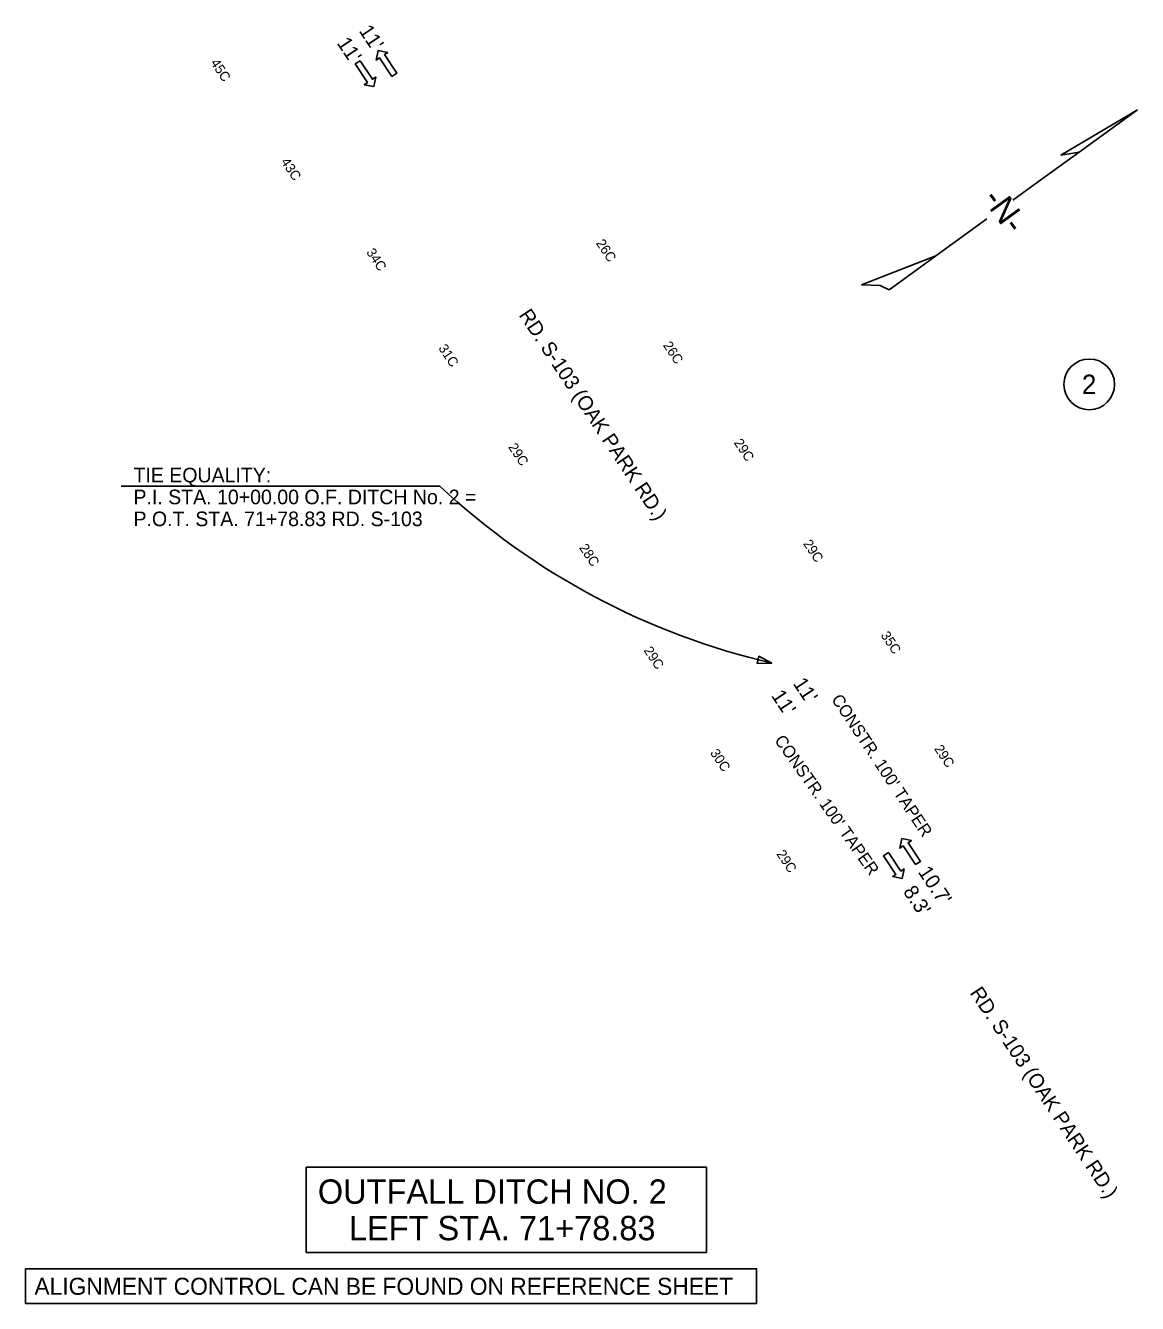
# Model space of a CAD drawing. Extents: x 1964850 to 1967424, y 1116563 to 1122204.
# Drawn here: x 1966637 to 1967094, y 1121679 to 1122204 of the extents above; entities that cross this region are included whole.
import ezdxf

# ---------------------------------------------------------------- set-up
doc = ezdxf.new("R2010")
doc.units = 0
for name, color, linetype in [('RD_EX_DV_TX_Prop', 7, 'Continuous'), ('RD_EX_Misc', 7, 'Continuous'), ('RD_HC_Data', 7, 'Continuous'), ('RD_PD_Final_LnLine', 7, 'Continuous'), ('RD_PD_Final_TX', 7, 'Continuous'), ('RD_PD_TX_CstnLmt', 7, 'Continuous'), ('RD_Sketch1', 7, 'Continuous'), ('RD_TX_Misc2', 7, 'Continuous'), ('RD_TX_RoadID', 7, 'Continuous')]:
    doc.layers.add(name, color=color, linetype=linetype)

msp = doc.modelspace()

# ---------------------------------------------------------------- linework, layer by layer
at = {"layer": 'RD_EX_DV_TX_Prop'}
msp.add_circle((1967074, 1122056.86), 10.43, dxfattribs=at)
at = {"layer": 'RD_EX_Misc'}
for p, q in [((1967062.37, 1122151.06), (1967093.8, 1122169.71)), ((1967093.8, 1122169.71), (1967069.8, 1122152.32)), ((1967069.8, 1122152.32), (1967053.16, 1122140.27)), ((1967069.8, 1122152.32), (1967062.37, 1122151.06)), ((1967053.16, 1122140.27), (1967042.55, 1122132.58)), ((1967031.96, 1122124.91), (1967010.99, 1122109.72)), ((1966980.45, 1122097.77), (1967010.99, 1122109.72)), ((1967007.81, 1122107.41), (1966991.74, 1122095.77)), ((1967010.99, 1122109.72), (1967007.81, 1122107.41))]:
    msp.add_line(p, q, dxfattribs=at)
msp.add_lwpolyline([(1966991.74, 1122095.77), (1966988.09, 1122097.5), (1966980.45, 1122097.77)], dxfattribs=at)
at = {"layer": 'RD_HC_Data'}
msp.add_line((1966807.1, 1122015.09), (1966676.23, 1122015.09), dxfattribs=at)
msp.add_lwpolyline([(1966937.53, 1121942.12), (1966943.53, 1121942.33), (1966938.23, 1121945.15)], close=True, dxfattribs=at)
msp.add_arc((1967010.89, 1122232.89), 298.27, 226.9031, 256.9482, dxfattribs=at)
at = {"layer": 'RD_PD_Final_LnLine'}
for points in [[(1966774.32, 1122189.89), (1966772.32, 1122188.56), (1966777.4, 1122180.93), (1966776.05, 1122180.02), (1966779.97, 1122179.24), (1966780.76, 1122183.16), (1966779.4, 1122182.26)], [(1966787.44, 1122183.43), (1966789.44, 1122184.76), (1966784.36, 1122192.39), (1966785.71, 1122193.3), (1966781.79, 1122194.08), (1966781, 1122190.16), (1966782.36, 1122191.06)], [(1967002.64, 1121859.5), (1967004.64, 1121860.83), (1966999.56, 1121868.47), (1967000.92, 1121869.37), (1966996.99, 1121870.16), (1966996.21, 1121866.24), (1966997.56, 1121867.14)], [(1966991.49, 1121864.44), (1966989.49, 1121863.11), (1966994.58, 1121855.47), (1966993.22, 1121854.57), (1966997.14, 1121853.78), (1966997.93, 1121857.71), (1966996.57, 1121856.8)]]:
    msp.add_lwpolyline(points, close=True, dxfattribs=at)
at = {"layer": 'RD_Sketch1'}
msp.add_lwpolyline([(1966636.88, 1121693.39), (1966937.31, 1121693.39), (1966937.31, 1121679.13), (1966636.88, 1121679.13)], close=True, dxfattribs=at)
at = {"layer": 'RD_TX_Misc2'}
msp.add_lwpolyline([(1966752.2, 1121735.1), (1966916.66, 1121735.1), (1966916.66, 1121700.1), (1966752.2, 1121700.1)], close=True, dxfattribs=at)

# ---------------------------------------------------------------- texts
at = {"layer": 'RD_EX_DV_TX_Prop'}
msp.add_text('2', height=8, dxfattribs=at).set_placement((1967070.98, 1122052.86))
at = {"layer": 'RD_EX_Misc'}
msp.add_text('-N-', height=10, rotation=305.9228, dxfattribs=at).set_placement((1967029.94, 1122133.06))
at = {"layer": 'RD_HC_Data'}
for s, p in [('TIE EQUALITY:', (1966681.23, 1122016.59)), ('P.I. STA. 10+00.00 O.F. DITCH No. 2 =', (1966681.23, 1122007.59)), ('P.O.T. STA. 71+78.83 RD. S-103', (1966681.23, 1121998.59))]:
    msp.add_text(s, height=6, dxfattribs=at).set_placement(p)
at = {"layer": 'RD_PD_Final_TX'}
for s, height, rotation, p in [("11'", 6, 303.6494, (1966773.67, 1122202.19)), ("11'", 6, 303.6494, (1966764.6, 1122197.13)), ("11'", 6, 303.6494, (1966952.05, 1121933.92)), ("11'", 6, 303.6494, (1966943.12, 1121928.91)), ("CONSTR. 100' TAPER", 5, 303.5003, (1966967.84, 1121927.46)), ("CONSTR. 100' TAPER", 5, 305.2108, (1966944.4, 1121910.58)), ("10.7'", 6, 303.6494, (1967003.41, 1121856.47)), ("8.3'", 6, 303.6494, (1966997.29, 1121848.39))]:
    msp.add_text(s, height=height, rotation=rotation, dxfattribs=at).set_placement(p)
at = {"layer": 'RD_PD_TX_CstnLmt'}
for s, p in [('45C', (1966712.69, 1122189.02)), ('43C', (1966741.63, 1122148.37)), ('26C', (1966871.12, 1122114.89)), ('34C', (1966776.73, 1122111.17)), ('31C', (1966806.36, 1122071.76)), ('26C', (1966898.67, 1122072.92)), ('29C', (1966835.07, 1122031.09)), ('29C', (1966927.8, 1122032.91)), ('28C', (1966864.2, 1121989.74)), ('29C', (1966956.25, 1121991.43)), ('35C', (1966988.15, 1121953.75)), ('29C', (1966890.74, 1121947.5)), ('30C', (1966918.03, 1121905.42)), ('29C', (1967010.11, 1121907.11)), ('29C', (1966945.29, 1121863.87))]:
    msp.add_text(s, height=4, rotation=303.6494, dxfattribs=at).set_placement(p)
at = {"layer": 'RD_Sketch1'}
msp.add_text('ALIGNMENT CONTROL CAN BE FOUND ON REFERENCE SHEET', height=7, dxfattribs=at).set_placement((1966640.53, 1121682.68))
at = {"layer": 'RD_TX_Misc2'}
for s, p in [('OUTFALL DITCH NO. 2', (1966756.99, 1121720.1)), ('LEFT STA. 71+78.83', (1966769.78, 1121705.1))]:
    msp.add_text(s, height=10, dxfattribs=at).set_placement(p)
at = {"layer": 'RD_TX_RoadID'}
for p in [(1966839.37, 1122085.35), (1967024.71, 1121806.77)]:
    msp.add_text('RD. S-103 (OAK PARK RD.)', height=6, rotation=303.6494, dxfattribs=at).set_placement(p)

doc.saveas('drawing.dxf')
